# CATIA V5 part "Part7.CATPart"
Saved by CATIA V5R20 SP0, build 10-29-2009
Part number: 9FP1406M5
Revision: ANY
Definition: UNKNOWN
Nomenclature: 9FP1406M5
Source: Unknown
Bounding box of the stored display mesh (mm): x -6.727 to 6.727, y 0 to 6, z -6.9 to 6.9
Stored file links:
  C:\Users\Utente\Desktop\IO LAVORO\3D X SITO CF\CUMSA\3D files PW\pw081230\pw081230_injection\Part7.CATPart
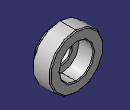
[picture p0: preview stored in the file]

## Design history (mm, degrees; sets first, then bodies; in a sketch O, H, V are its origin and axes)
Body1 "Chaflán1" (main body)
  Solid1: solid without history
